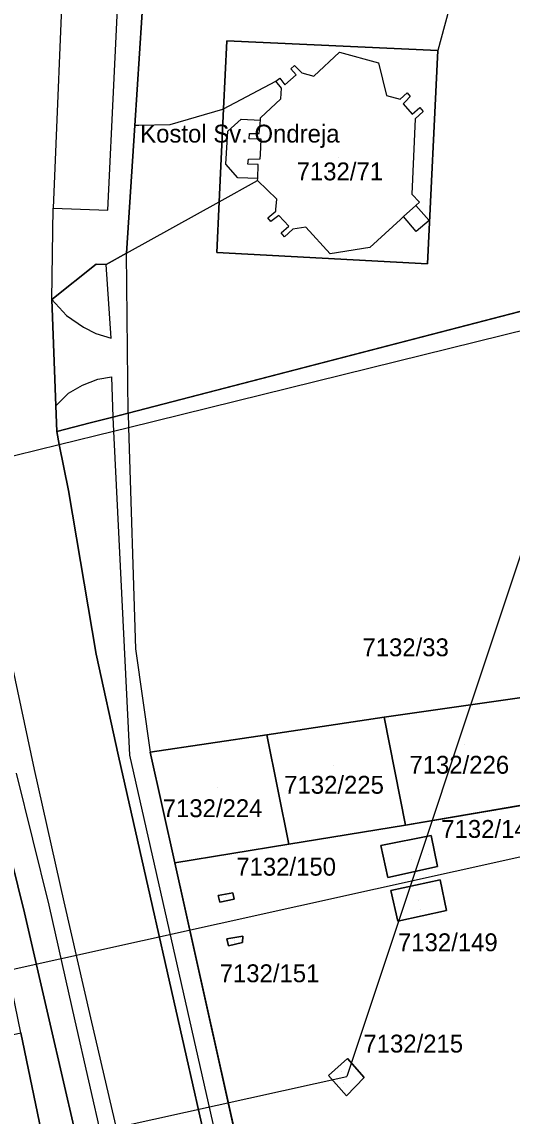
# Model space of a CAD drawing. Extents: x -266199 to -261993, y -1239047 to -1235108.
# Drawn here: x -263519.6 to -263464.7, y -1236679 to -1236556.5 of the extents above; entities that cross this region are included whole.
import ezdxf

# ---------------------------------------------------------------- set-up
doc = ezdxf.new("R2010")
doc.units = 0
for name, color, linetype in [('body_kn', 7, 'Continuous'), ('kladpar_druhypozemkov', 7, 'Continuous'), ('kladpar_hranice', 7, 'Continuous'), ('kladpar_parcelnecisla', 7, 'Continuous'), ('kladpar_plochy', 7, 'Continuous'), ('kladpar_sipky', 7, 'Continuous'), ('linie', 7, 'Continuous'), ('popisy', 7, 'Continuous'), ('zappar_hrandruhpozemk', 7, 'Continuous')]:
    doc.layers.add(name, color=color, linetype=linetype)

msp = doc.modelspace()

# ---------------------------------------------------------------- linework, layer by layer
at = {"layer": 'body_kn'}
for p, q in [((-263496.65, -1236558.64), (-263496.65, -1236558.64)), ((-263496.65, -1236558.64), (-263496.65, -1236558.64)), ((-263484.06, -1236559.9), (-263484.06, -1236559.9)), ((-263484.06, -1236559.9), (-263484.06, -1236559.9)), ((-263473.03, -1236559.71), (-263473.03, -1236559.71)), ((-263473.03, -1236559.71), (-263473.03, -1236559.71)), ((-263479.68, -1236561.1), (-263479.68, -1236561.1)), ((-263489.48, -1236561.74), (-263489.48, -1236561.74)), ((-263489.08, -1236561.38), (-263489.08, -1236561.38)), ((-263488.24, -1236562.21), (-263488.24, -1236562.21)), ((-263491.16, -1236563.15), (-263491.16, -1236563.15)), ((-263491.16, -1236563.15), (-263491.16, -1236563.15)), ((-263490.72, -1236562.82), (-263490.72, -1236562.82)), ((-263490.15, -1236563.55), (-263490.15, -1236563.55)), ((-263488.9, -1236562.44), (-263488.9, -1236562.44)), ((-263486.93, -1236562.57), (-263486.93, -1236562.57)), ((-263490.53, -1236563.94), (-263490.53, -1236563.94)), ((-263478.78, -1236564.75), (-263478.78, -1236564.75)), ((-263476.49, -1236564.44), (-263476.49, -1236564.44)), ((-263476.15, -1236564.86), (-263476.15, -1236564.86)), ((-263490.62, -1236565.13), (-263490.62, -1236565.13)), ((-263477.27, -1236565.15), (-263477.27, -1236565.15)), ((-263476.91, -1236565.66), (-263476.91, -1236565.66)), ((-263476.67, -1236565.41), (-263476.67, -1236565.41)), ((-263475.05, -1236566.08), (-263475.05, -1236566.08)), ((-263497.14, -1236566.3), (-263497.14, -1236566.3)), ((-263497.01, -1236566.23), (-263497.01, -1236566.23)), ((-263497.01, -1236566.23), (-263497.01, -1236566.23)), ((-263492.88, -1236567.25), (-263492.88, -1236567.25)), ((-263475.9, -1236566.84), (-263475.9, -1236566.84)), ((-263474.67, -1236566.52), (-263474.67, -1236566.52)), ((-263506.94, -1236568.11), (-263506.94, -1236568.11)), ((-263506.5, -1236568.1), (-263506.5, -1236568.1)), ((-263503.04, -1236568.02), (-263503.04, -1236568.02)), ((-263495.03, -1236567.39), (-263495.03, -1236567.39)), ((-263492.9, -1236567.5), (-263492.9, -1236567.5)), ((-263492.9, -1236567.5), (-263492.9, -1236567.5)), ((-263475.58, -1236567.35), (-263475.58, -1236567.35)), ((-263496.55, -1236568.72), (-263496.55, -1236568.72)), ((-263494.14, -1236569.58), (-263494.14, -1236569.58)), ((-263494.12, -1236569), (-263494.12, -1236569)), ((-263493.03, -1236569.01), (-263493.03, -1236569.01)), ((-263492.79, -1236569.64), (-263492.79, -1236569.64)), ((-263494.24, -1236571.86), (-263494.24, -1236571.86)), ((-263492.92, -1236571.84), (-263492.92, -1236571.84)), ((-263492.89, -1236571.34), (-263492.89, -1236571.34)), ((-263496.77, -1236572.43), (-263496.77, -1236572.43)), ((-263494.3, -1236572.43), (-263494.3, -1236572.43)), ((-263493.15, -1236572.45), (-263493.15, -1236572.45)), ((-263495.42, -1236573.96), (-263495.42, -1236573.96)), ((-263493.2, -1236574.27), (-263493.2, -1236574.27)), ((-263493.19, -1236574.02), (-263493.19, -1236574.02)), ((-263493.19, -1236574.02), (-263493.19, -1236574.02)), ((-263475.97, -1236575.78), (-263475.97, -1236575.78)), ((-263497.51, -1236576.65), (-263497.51, -1236576.65)), ((-263497.51, -1236576.65), (-263497.51, -1236576.65)), ((-263491.07, -1236576.33), (-263491.07, -1236576.33)), ((-263491.07, -1236576.33), (-263491.07, -1236576.33)), ((-263475.5, -1236577.06), (-263475.5, -1236577.06)), ((-263475.5, -1236577.06), (-263475.5, -1236577.06)), ((-263475.1, -1236576.69), (-263475.1, -1236576.69)), ((-263516.09, -1236577.37), (-263516.09, -1236577.37)), ((-263516.09, -1236577.37), (-263516.09, -1236577.37)), ((-263509.95, -1236577.58), (-263509.95, -1236577.58)), ((-263491.16, -1236577.68), (-263491.16, -1236577.68)), ((-263491.15, -1236577.51), (-263491.15, -1236577.51)), ((-263490.82, -1236578.17), (-263490.82, -1236578.17)), ((-263476.87, -1236578.3), (-263476.87, -1236578.3)), ((-263476.87, -1236578.3), (-263476.87, -1236578.3)), ((-263492.05, -1236578.43), (-263492.05, -1236578.43)), ((-263491.73, -1236578.86), (-263491.73, -1236578.86)), ((-263489.73, -1236579.36), (-263489.73, -1236579.36)), ((-263487.82, -1236579.47), (-263487.82, -1236579.47)), ((-263477.23, -1236578.62), (-263477.23, -1236578.62)), ((-263474, -1236578.75), (-263474, -1236578.75)), ((-263490.56, -1236580.13), (-263490.56, -1236580.13)), ((-263490.18, -1236580.55), (-263490.18, -1236580.55)), ((-263489.27, -1236579.71), (-263489.27, -1236579.71)), ((-263475.45, -1236579.97), (-263475.45, -1236579.97)), ((-263480.66, -1236581.75), (-263480.66, -1236581.75)), ((-263507.88, -1236582.39), (-263507.88, -1236582.39)), ((-263507.88, -1236582.39), (-263507.88, -1236582.39)), ((-263497.78, -1236582.3), (-263497.78, -1236582.3)), ((-263485.09, -1236582.47), (-263485.09, -1236582.47)), ((-263511.28, -1236583.61), (-263511.28, -1236583.61)), ((-263510.14, -1236583.67), (-263510.14, -1236583.67)), ((-263474.2, -1236583.57), (-263474.2, -1236583.57)), ((-263516.23, -1236587.58), (-263516.23, -1236587.58)), ((-263516.23, -1236587.58), (-263516.23, -1236587.58)), ((-263514.58, -1236589.37), (-263514.58, -1236589.37)), ((-263512.7, -1236590.68), (-263512.7, -1236590.68)), ((-263511.31, -1236591.38), (-263511.31, -1236591.38)), ((-263509.59, -1236591.92), (-263509.59, -1236591.92)), ((-263511.07, -1236596.5), (-263511.07, -1236596.5)), ((-263509.54, -1236596.23), (-263509.54, -1236596.23)), ((-263512.81, -1236597.17), (-263512.81, -1236597.17)), ((-263514.36, -1236598.08), (-263514.36, -1236598.08)), ((-263515.78, -1236599.49), (-263515.78, -1236599.49)), ((-263515.78, -1236599.49), (-263515.78, -1236599.49)), ((-263507.69, -1236600.3), (-263507.69, -1236600.3)), ((-263507.69, -1236600.3), (-263507.69, -1236600.3)), ((-263511.92, -1236601.4), (-263511.92, -1236601.4)), ((-263509.41, -1236600.75), (-263509.41, -1236600.75)), ((-263509.41, -1236600.75), (-263509.41, -1236600.75)), ((-263515.67, -1236602.37), (-263515.67, -1236602.37)), ((-263509.33, -1236602.31), (-263509.33, -1236602.31)), ((-263509.33, -1236602.31), (-263509.33, -1236602.31)), ((-263507.64, -1236601.9), (-263507.64, -1236601.9)), ((-263507.64, -1236601.9), (-263507.64, -1236601.9)), ((-263515.39, -1236603.81), (-263515.39, -1236603.81)), ((-263514.37, -1236608.96), (-263514.37, -1236608.96)), ((-263511.25, -1236627.28), (-263511.25, -1236627.28)), ((-263506.88, -1236626.69), (-263506.88, -1236626.69)), ((-263479.06, -1236634.34), (-263479.06, -1236634.34)), ((-263479.06, -1236634.34), (-263479.06, -1236634.34)), ((-263492.17, -1236636.29), (-263492.17, -1236636.29)), ((-263505.23, -1236638.24), (-263505.23, -1236638.24)), ((-263505.23, -1236638.24), (-263505.23, -1236638.24)), ((-263508.75, -1236638.71), (-263508.75, -1236638.71)), ((-263507.54, -1236638.59), (-263507.54, -1236638.59)), ((-263518.2, -1236640.2), (-263518.2, -1236640.2)), ((-263476.66, -1236646.41), (-263476.66, -1236646.41)), ((-263473.79, -1236647.58), (-263473.79, -1236647.58)), ((-263489.73, -1236648.54), (-263489.73, -1236648.54)), ((-263489.73, -1236648.54), (-263489.73, -1236648.54)), ((-263479.41, -1236648.71), (-263479.41, -1236648.71)), ((-263502.47, -1236650.62), (-263502.47, -1236650.62)), ((-263473.08, -1236651.03), (-263473.08, -1236651.03)), ((-263478.62, -1236652.26), (-263478.62, -1236652.26)), ((-263478.62, -1236652.26), (-263478.62, -1236652.26)), ((-263472.78, -1236652.52), (-263472.78, -1236652.52)), ((-263495.98, -1236654), (-263495.98, -1236654)), ((-263478.29, -1236653.75), (-263478.29, -1236653.75)), ((-263516.52, -1236655.38), (-263516.52, -1236655.38)), ((-263514.9, -1236654.99), (-263514.9, -1236654.99)), ((-263497.6, -1236654.28), (-263497.6, -1236654.28)), ((-263497.43, -1236655.03), (-263497.43, -1236655.03)), ((-263497.43, -1236655.03), (-263497.43, -1236655.03)), ((-263495.81, -1236654.7), (-263495.81, -1236654.7)), ((-263519.28, -1236656.23), (-263519.28, -1236656.23)), ((-263472.07, -1236655.96), (-263472.07, -1236655.96)), ((-263477.53, -1236657.18), (-263477.53, -1236657.18)), ((-263477.53, -1236657.18), (-263477.53, -1236657.18)), ((-263496.64, -1236659.15), (-263496.64, -1236659.15)), ((-263494.87, -1236658.85), (-263494.87, -1236658.85)), ((-263496.45, -1236659.92), (-263496.45, -1236659.92)), ((-263496.45, -1236659.92), (-263496.45, -1236659.92)), ((-263494.89, -1236659.57), (-263494.89, -1236659.57)), ((-263516.42, -1236668.71), (-263516.42, -1236668.71)), ((-263513.62, -1236668.33), (-263513.62, -1236668.33)), ((-263511.89, -1236667.97), (-263511.89, -1236667.97)), ((-263483.16, -1236672.55), (-263483.16, -1236672.55)), ((-263485.27, -1236674.43), (-263485.27, -1236674.43)), ((-263483.21, -1236674.56), (-263483.21, -1236674.56)), ((-263483.21, -1236674.56), (-263483.21, -1236674.56)), ((-263481.27, -1236674.67), (-263481.27, -1236674.67)), ((-263483.26, -1236676.7), (-263483.26, -1236676.7)), ((-263483.26, -1236676.7), (-263483.26, -1236676.7))]:
    msp.add_line(p, q, dxfattribs=at)
at = {"layer": 'kladpar_druhypozemkov'}
for p, q in [((-263484.14, -1236571.71), (-263484.14, -1236571.71)), ((-263475.35, -1236625.52), (-263475.35, -1236625.52)), ((-263470.04, -1236637.43), (-263470.04, -1236637.43)), ((-263484.73, -1236639.75), (-263484.73, -1236639.75)), ((-263497.72, -1236642.18), (-263497.72, -1236642.18)), ((-263476.03, -1236650.21), (-263476.03, -1236650.21)), ((-263496.75, -1236654.55), (-263496.75, -1236654.55)), ((-263475.2, -1236654.87), (-263475.2, -1236654.87)), ((-263495.79, -1236659.29), (-263495.79, -1236659.29)), ((-263475.87, -1236670), (-263475.87, -1236670)), ((-263483.79, -1236674.01), (-263483.79, -1236674.01))]:
    msp.add_line(p, q, dxfattribs=at)
at = {"layer": 'kladpar_hranice'}
for p, q in [((-263396.48, -1236274.15), (-263473.03, -1236559.71)), ((-263497.36, -1236689.19), (-263508.75, -1236638.71))]:
    msp.add_line(p, q, dxfattribs=at)
for points in [[(-263502.57, -1236483.44), (-263505.62, -1236547.93), (-263506.94, -1236568.11), (-263507.88, -1236582.39)], [(-263507.88, -1236582.39), (-263506.94, -1236568.11), (-263505.62, -1236547.93), (-263502.57, -1236483.44), (-263493.38, -1236483.86)], [(-263444.22, -1236548.96), (-263442.35, -1236561.28), (-263441.75, -1236565.24), (-263441.38, -1236567.71), (-263441.21, -1236568.34), (-263456.21, -1236570.33), (-263457.14, -1236570.46), (-263455.53, -1236586.76), (-263456.81, -1236587.09), (-263459.98, -1236587.91), (-263507.69, -1236600.3), (-263509.41, -1236600.75), (-263511.92, -1236601.4), (-263515.67, -1236602.37), (-263515.78, -1236599.49), (-263516.23, -1236587.58), (-263511.28, -1236583.61), (-263510.14, -1236583.67), (-263507.88, -1236582.39)], [(-263496.65, -1236558.64), (-263473.03, -1236559.71), (-263474.2, -1236583.57), (-263497.78, -1236582.3), (-263497.51, -1236576.65), (-263497.01, -1236566.23), (-263496.65, -1236558.64)], [(-263473.03, -1236559.71), (-263496.65, -1236558.64), (-263497.01, -1236566.23), (-263497.51, -1236576.65), (-263497.78, -1236582.3), (-263474.2, -1236583.57), (-263473.03, -1236559.71)], [(-263507.88, -1236582.39), (-263510.14, -1236583.67), (-263511.28, -1236583.61), (-263516.23, -1236587.58), (-263515.78, -1236599.49), (-263515.67, -1236602.37), (-263515.39, -1236603.81), (-263514.37, -1236608.96), (-263511.25, -1236627.28), (-263508.75, -1236638.71), (-263497.36, -1236689.19)], [(-263508.75, -1236638.71), (-263511.25, -1236627.28), (-263514.37, -1236608.96), (-263515.39, -1236603.81), (-263515.67, -1236602.37), (-263511.92, -1236601.4), (-263509.41, -1236600.75), (-263507.69, -1236600.3), (-263459.98, -1236587.91)], [(-263514.71, -1236693.75), (-263519.71, -1236669.67), (-263522.32, -1236657.09), (-263532.95, -1236608.14), (-263533.22, -1236606.88), (-263531.22, -1236606.77), (-263529.42, -1236607.27), (-263529.2, -1236607.33), (-263526.57, -1236622.05), (-263523.07, -1236640.98), (-263519.28, -1236656.23), (-263516.42, -1236668.71), (-263510.88, -1236692.59), (-263513.28, -1236692.44), (-263514.71, -1236693.75)], [(-263505.23, -1236638.24), (-263502.47, -1236650.62), (-263493.76, -1236689.75), (-263461.56, -1236681.97), (-263460.11, -1236680.81), (-263459.17, -1236678.81), (-263459.01, -1236676.99), (-263463.61, -1236657), (-263445.44, -1236652.7), (-263447.9, -1236641.65), (-263450.33, -1236632.11), (-263452.46, -1236630.28), (-263463.11, -1236632.06), (-263479.06, -1236634.34), (-263492.17, -1236636.29), (-263505.23, -1236638.24)], [(-263479.06, -1236634.34), (-263463.11, -1236632.06), (-263460.84, -1236643.71), (-263476.66, -1236646.41), (-263479.06, -1236634.34)], [(-263489.73, -1236648.54), (-263492.17, -1236636.29), (-263479.06, -1236634.34), (-263476.66, -1236646.41), (-263489.73, -1236648.54)], [(-263505.23, -1236638.24), (-263492.17, -1236636.29), (-263489.73, -1236648.54), (-263502.47, -1236650.62), (-263505.23, -1236638.24)], [(-263510.88, -1236692.59), (-263516.42, -1236668.71), (-263519.28, -1236656.23), (-263523.07, -1236640.98)], [(-263493.76, -1236689.75), (-263502.47, -1236650.62), (-263489.73, -1236648.54), (-263476.66, -1236646.41), (-263460.84, -1236643.71), (-263447.9, -1236641.65), (-263445.44, -1236652.7), (-263463.61, -1236657), (-263459.01, -1236676.99), (-263459.17, -1236678.81), (-263460.11, -1236680.81), (-263461.56, -1236681.97), (-263493.76, -1236689.75)], [(-263479.41, -1236648.71), (-263478.62, -1236652.26), (-263473.08, -1236651.03), (-263473.79, -1236647.58), (-263479.41, -1236648.71)], [(-263478.62, -1236652.26), (-263479.41, -1236648.71), (-263473.79, -1236647.58), (-263473.08, -1236651.03), (-263478.62, -1236652.26)], [(-263478.29, -1236653.75), (-263477.53, -1236657.18), (-263472.07, -1236655.96), (-263472.78, -1236652.52), (-263478.29, -1236653.75)], [(-263477.53, -1236657.18), (-263478.29, -1236653.75), (-263472.78, -1236652.52), (-263472.07, -1236655.96), (-263477.53, -1236657.18)], [(-263497.6, -1236654.28), (-263497.43, -1236655.03), (-263495.81, -1236654.7), (-263495.98, -1236654), (-263497.6, -1236654.28)], [(-263497.43, -1236655.03), (-263497.6, -1236654.28), (-263495.98, -1236654), (-263495.81, -1236654.7), (-263497.43, -1236655.03)], [(-263496.64, -1236659.15), (-263496.45, -1236659.92), (-263494.89, -1236659.57), (-263494.87, -1236658.85), (-263496.64, -1236659.15)], [(-263496.45, -1236659.92), (-263496.64, -1236659.15), (-263494.87, -1236658.85), (-263494.89, -1236659.57), (-263496.45, -1236659.92)], [(-263531.42, -1236698.79), (-263530.05, -1236672), (-263519.71, -1236669.67), (-263514.71, -1236693.75), (-263531.42, -1236698.79)], [(-263485.27, -1236674.43), (-263483.26, -1236676.7), (-263481.27, -1236674.67), (-263483.16, -1236672.55), (-263485.27, -1236674.43)], [(-263483.26, -1236676.7), (-263485.27, -1236674.43), (-263483.16, -1236672.55), (-263481.27, -1236674.67), (-263483.26, -1236676.7)]]:
    msp.add_lwpolyline(points, dxfattribs=at)
at = {"layer": 'kladpar_plochy'}
for p, q in [((-263506.94, -1236568.11), (-263505.62, -1236547.93)), ((-263496.65, -1236558.64), (-263497.01, -1236566.23)), ((-263473.03, -1236559.71), (-263496.65, -1236558.64)), ((-263474.2, -1236583.57), (-263473.03, -1236559.71)), ((-263497.01, -1236566.23), (-263497.51, -1236576.65)), ((-263507.88, -1236582.39), (-263506.94, -1236568.11)), ((-263497.51, -1236576.65), (-263497.78, -1236582.3)), ((-263510.14, -1236583.67), (-263507.88, -1236582.39)), ((-263497.78, -1236582.3), (-263474.2, -1236583.57)), ((-263516.23, -1236587.58), (-263511.28, -1236583.61)), ((-263511.28, -1236583.61), (-263510.14, -1236583.67)), ((-263515.78, -1236599.49), (-263516.23, -1236587.58)), ((-263507.69, -1236600.3), (-263459.98, -1236587.91)), ((-263459.98, -1236587.91), (-263507.69, -1236600.3)), ((-263515.67, -1236602.37), (-263515.78, -1236599.49)), ((-263509.41, -1236600.75), (-263507.69, -1236600.3)), ((-263507.69, -1236600.3), (-263509.41, -1236600.75)), ((-263515.67, -1236602.37), (-263511.92, -1236601.4)), ((-263511.92, -1236601.4), (-263515.67, -1236602.37)), ((-263511.92, -1236601.4), (-263509.41, -1236600.75)), ((-263509.41, -1236600.75), (-263511.92, -1236601.4)), ((-263515.39, -1236603.81), (-263515.67, -1236602.37)), ((-263514.37, -1236608.96), (-263515.39, -1236603.81)), ((-263511.25, -1236627.28), (-263514.37, -1236608.96)), ((-263508.75, -1236638.71), (-263511.25, -1236627.28)), ((-263463.11, -1236632.06), (-263479.06, -1236634.34)), ((-263479.06, -1236634.34), (-263492.17, -1236636.29)), ((-263492.17, -1236636.29), (-263505.23, -1236638.24)), ((-263505.23, -1236638.24), (-263502.47, -1236650.62)), ((-263497.36, -1236689.19), (-263508.75, -1236638.71)), ((-263476.66, -1236646.41), (-263460.84, -1236643.71)), ((-263489.73, -1236648.54), (-263476.66, -1236646.41)), ((-263473.79, -1236647.58), (-263479.41, -1236648.71)), ((-263473.08, -1236651.03), (-263473.79, -1236647.58)), ((-263502.47, -1236650.62), (-263489.73, -1236648.54)), ((-263479.41, -1236648.71), (-263478.62, -1236652.26)), ((-263493.76, -1236689.75), (-263502.47, -1236650.62)), ((-263502.47, -1236650.62), (-263493.76, -1236689.75)), ((-263478.62, -1236652.26), (-263473.08, -1236651.03)), ((-263472.78, -1236652.52), (-263478.29, -1236653.75)), ((-263472.07, -1236655.96), (-263472.78, -1236652.52)), ((-263495.98, -1236654), (-263497.6, -1236654.28)), ((-263495.81, -1236654.7), (-263495.98, -1236654)), ((-263478.29, -1236653.75), (-263477.53, -1236657.18)), ((-263497.6, -1236654.28), (-263497.43, -1236655.03)), ((-263497.43, -1236655.03), (-263495.81, -1236654.7)), ((-263477.53, -1236657.18), (-263472.07, -1236655.96)), ((-263494.87, -1236658.85), (-263496.64, -1236659.15)), ((-263496.64, -1236659.15), (-263496.45, -1236659.92)), ((-263494.89, -1236659.57), (-263494.87, -1236658.85)), ((-263496.45, -1236659.92), (-263494.89, -1236659.57)), ((-263483.16, -1236672.55), (-263485.27, -1236674.43)), ((-263481.27, -1236674.67), (-263483.16, -1236672.55)), ((-263485.27, -1236674.43), (-263483.26, -1236676.7)), ((-263483.26, -1236676.7), (-263481.27, -1236674.67))]:
    msp.add_line(p, q, dxfattribs=at)
for points in [[(-263501.28, -1236460.62), (-263502.42, -1236480.32), (-263502.57, -1236483.44), (-263505.62, -1236547.93), (-263506.94, -1236568.11), (-263507.88, -1236582.39), (-263510.14, -1236583.67), (-263511.28, -1236583.61), (-263516.23, -1236587.58), (-263515.78, -1236599.49), (-263515.67, -1236602.37), (-263515.39, -1236603.81), (-263514.37, -1236608.96), (-263511.25, -1236627.28), (-263508.75, -1236638.71), (-263497.36, -1236689.19)], [(-263510.88, -1236692.59), (-263516.42, -1236668.71), (-263519.28, -1236656.23), (-263523.07, -1236640.98)]]:
    msp.add_lwpolyline(points, dxfattribs=at)
for points in [[(-263496.65, -1236558.64), (-263473.03, -1236559.71), (-263474.2, -1236583.57), (-263497.78, -1236582.3), (-263497.51, -1236576.65), (-263497.01, -1236566.23)], [(-263514.71, -1236693.75), (-263519.71, -1236669.67), (-263522.32, -1236657.09), (-263532.95, -1236608.14), (-263533.22, -1236606.88), (-263531.22, -1236606.77), (-263529.42, -1236607.27), (-263529.2, -1236607.33), (-263526.57, -1236622.05), (-263523.07, -1236640.98), (-263519.28, -1236656.23), (-263516.42, -1236668.71), (-263510.88, -1236692.59), (-263513.28, -1236692.44)], [(-263479.06, -1236634.34), (-263463.11, -1236632.06), (-263460.84, -1236643.71), (-263476.66, -1236646.41)], [(-263489.73, -1236648.54), (-263492.17, -1236636.29), (-263479.06, -1236634.34), (-263476.66, -1236646.41)], [(-263505.23, -1236638.24), (-263492.17, -1236636.29), (-263489.73, -1236648.54), (-263502.47, -1236650.62)], [(-263478.62, -1236652.26), (-263479.41, -1236648.71), (-263473.79, -1236647.58), (-263473.08, -1236651.03)], [(-263477.53, -1236657.18), (-263478.29, -1236653.75), (-263472.78, -1236652.52), (-263472.07, -1236655.96)], [(-263497.43, -1236655.03), (-263497.6, -1236654.28), (-263495.98, -1236654), (-263495.81, -1236654.7)], [(-263496.45, -1236659.92), (-263496.64, -1236659.15), (-263494.87, -1236658.85), (-263494.89, -1236659.57)], [(-263531.42, -1236698.79), (-263530.05, -1236672), (-263519.71, -1236669.67), (-263514.71, -1236693.75)], [(-263483.26, -1236676.7), (-263485.27, -1236674.43), (-263483.16, -1236672.55), (-263481.27, -1236674.67)]]:
    msp.add_lwpolyline(points, close=True, dxfattribs=at)
at = {"layer": 'kladpar_sipky'}
for p, q in [((-263474.05, -1236649.75), (-263474.05, -1236649.75)), ((-263496.71, -1236654.34), (-263496.71, -1236654.34)), ((-263474.93, -1236655.89), (-263474.93, -1236655.89)), ((-263495.74, -1236659.54), (-263495.74, -1236659.54)), ((-263483.57, -1236675.34), (-263483.57, -1236675.34))]:
    msp.add_line(p, q, dxfattribs=at)
at = {"layer": 'linie'}
for p in [(-263455.18, -1236590.24), (-263714.61, -1236725.54)]:
    msp.add_line(p, (-263483.21, -1236674.56), dxfattribs=at)
for points in [[(-263532.95, -1236608.14), (-263529.42, -1236607.27), (-263527.55, -1236606.81), (-263515.39, -1236603.81), (-263509.33, -1236602.31), (-263507.64, -1236601.9), (-263459.75, -1236590.08), (-263456.58, -1236589.3), (-263455.31, -1236588.99)], [(-263718.15, -1236705.82), (-263532.54, -1236665.19), (-263418.65, -1236639.94)]]:
    msp.add_lwpolyline(points, dxfattribs=at)
at = {"layer": 'zappar_hrandruhpozemk'}
for p, q in [((-263497.01, -1236566.23), (-263491.16, -1236563.15)), ((-263497.14, -1236566.3), (-263503.04, -1236568.02)), ((-263497.01, -1236566.23), (-263497.14, -1236566.3)), ((-263475.58, -1236567.35), (-263475.97, -1236575.78)), ((-263496.77, -1236572.43), (-263496.55, -1236568.72)), ((-263492.89, -1236571.34), (-263492.79, -1236569.64)), ((-263497.51, -1236576.65), (-263493.2, -1236574.27)), ((-263476.87, -1236578.3), (-263475.5, -1236577.06)), ((-263516.23, -1236587.58), (-263516.09, -1236577.37)), ((-263509.59, -1236591.92), (-263510.14, -1236583.67)), ((-263509.54, -1236596.23), (-263509.41, -1236600.75)), ((-263507.69, -1236600.3), (-263507.64, -1236601.9)), ((-263509.41, -1236600.75), (-263509.33, -1236602.31)), ((-263507.64, -1236601.9), (-263506.88, -1236626.69)), ((-263522.22, -1236621.42), (-263518.2, -1236640.2)), ((-263506.88, -1236626.69), (-263505.23, -1236638.24)), ((-263508.06, -1236692.63), (-263513.62, -1236668.33)), ((-263511.89, -1236667.97), (-263506.2, -1236692.46))]:
    msp.add_line(p, q, dxfattribs=at)
for points in [[(-263508.53, -1236548), (-263514.84, -1236547.63), (-263516.09, -1236577.37)], [(-263516.09, -1236577.37), (-263509.95, -1236577.58), (-263508.53, -1236548)], [(-263491.16, -1236563.15), (-263490.72, -1236562.82), (-263490.15, -1236563.55), (-263488.9, -1236562.44), (-263489.48, -1236561.74), (-263489.08, -1236561.38), (-263488.24, -1236562.21), (-263486.93, -1236562.57), (-263484.06, -1236559.9)], [(-263484.06, -1236559.9), (-263479.68, -1236561.1), (-263478.78, -1236564.75), (-263477.27, -1236565.15), (-263476.49, -1236564.44), (-263476.15, -1236564.86), (-263476.67, -1236565.41), (-263476.91, -1236565.66), (-263475.9, -1236566.84), (-263475.05, -1236566.08), (-263474.67, -1236566.52), (-263475.58, -1236567.35)], [(-263492.9, -1236567.5), (-263492.88, -1236567.25), (-263490.62, -1236565.13), (-263490.53, -1236563.94), (-263491.16, -1236563.15)], [(-263503.04, -1236568.02), (-263506.5, -1236568.1), (-263506.94, -1236568.11)], [(-263496.55, -1236568.72), (-263495.03, -1236567.39), (-263492.9, -1236567.5)], [(-263492.79, -1236569.64), (-263494.14, -1236569.58), (-263494.12, -1236569), (-263493.03, -1236569.01), (-263492.9, -1236567.5)], [(-263493.19, -1236574.02), (-263493.15, -1236572.45), (-263494.3, -1236572.43), (-263494.24, -1236571.86), (-263492.92, -1236571.84), (-263492.89, -1236571.34)], [(-263493.19, -1236574.02), (-263495.42, -1236573.96), (-263496.77, -1236572.43)], [(-263491.07, -1236576.33), (-263493.2, -1236574.27), (-263493.19, -1236574.02)], [(-263475.97, -1236575.78), (-263475.1, -1236576.69), (-263475.5, -1236577.06)], [(-263507.69, -1236600.3), (-263507.88, -1236582.39), (-263497.51, -1236576.65)], [(-263476.87, -1236578.3), (-263477.23, -1236578.62), (-263480.66, -1236581.75), (-263485.09, -1236582.47), (-263487.82, -1236579.47), (-263489.27, -1236579.71), (-263490.18, -1236580.55), (-263490.56, -1236580.13), (-263489.73, -1236579.36), (-263490.82, -1236578.17), (-263491.73, -1236578.86), (-263492.05, -1236578.43), (-263491.16, -1236577.68), (-263491.15, -1236577.51), (-263491.07, -1236576.33)], [(-263475.5, -1236577.06), (-263474, -1236578.75), (-263475.45, -1236579.97), (-263476.87, -1236578.3)], [(-263516.23, -1236587.58), (-263514.58, -1236589.37), (-263512.7, -1236590.68), (-263511.31, -1236591.38), (-263509.59, -1236591.92)], [(-263515.78, -1236599.49), (-263514.36, -1236598.08), (-263512.81, -1236597.17), (-263511.07, -1236596.5), (-263509.54, -1236596.23)], [(-263509.33, -1236602.31), (-263507.54, -1236638.59), (-263495.71, -1236690.85)], [(-263529.42, -1236607.27), (-263527.55, -1236606.81), (-263515.39, -1236603.81)], [(-263513.62, -1236668.33), (-263516.52, -1236655.38), (-263520.16, -1236640.6)], [(-263518.2, -1236640.2), (-263514.9, -1236654.99), (-263511.89, -1236667.97)]]:
    msp.add_lwpolyline(points, dxfattribs=at)

# ---------------------------------------------------------------- texts
at = {"layer": 'kladpar_parcelnecisla'}
for s, p in [('7132/71', (-263488.84, -1236574.24)), ('7132/33', (-263481.48, -1236627.51)), ('7132/226', (-263476.22, -1236640.66)), ('7132/225', (-263490.23, -1236642.9)), ('7132/224', (-263503.82, -1236645.52)), ('7132/148', (-263472.66, -1236647.84)), ('7132/150', (-263495.59, -1236652.07)), ('7132/149', (-263477.5, -1236660.53)), ('7132/151', (-263497.45, -1236664)), ('7132/215', (-263481.37, -1236671.87))]:
    msp.add_text(s, height=2, dxfattribs=at).set_placement(p)
at = {"layer": 'popisy'}
msp.add_text('Kostol Sv. Ondreja', height=2, dxfattribs=at).set_placement((-263506.34, -1236570.01))

doc.saveas('drawing.dxf')
